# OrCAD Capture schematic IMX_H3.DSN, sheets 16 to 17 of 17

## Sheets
16 PAGE17 - discrete power supply: size C
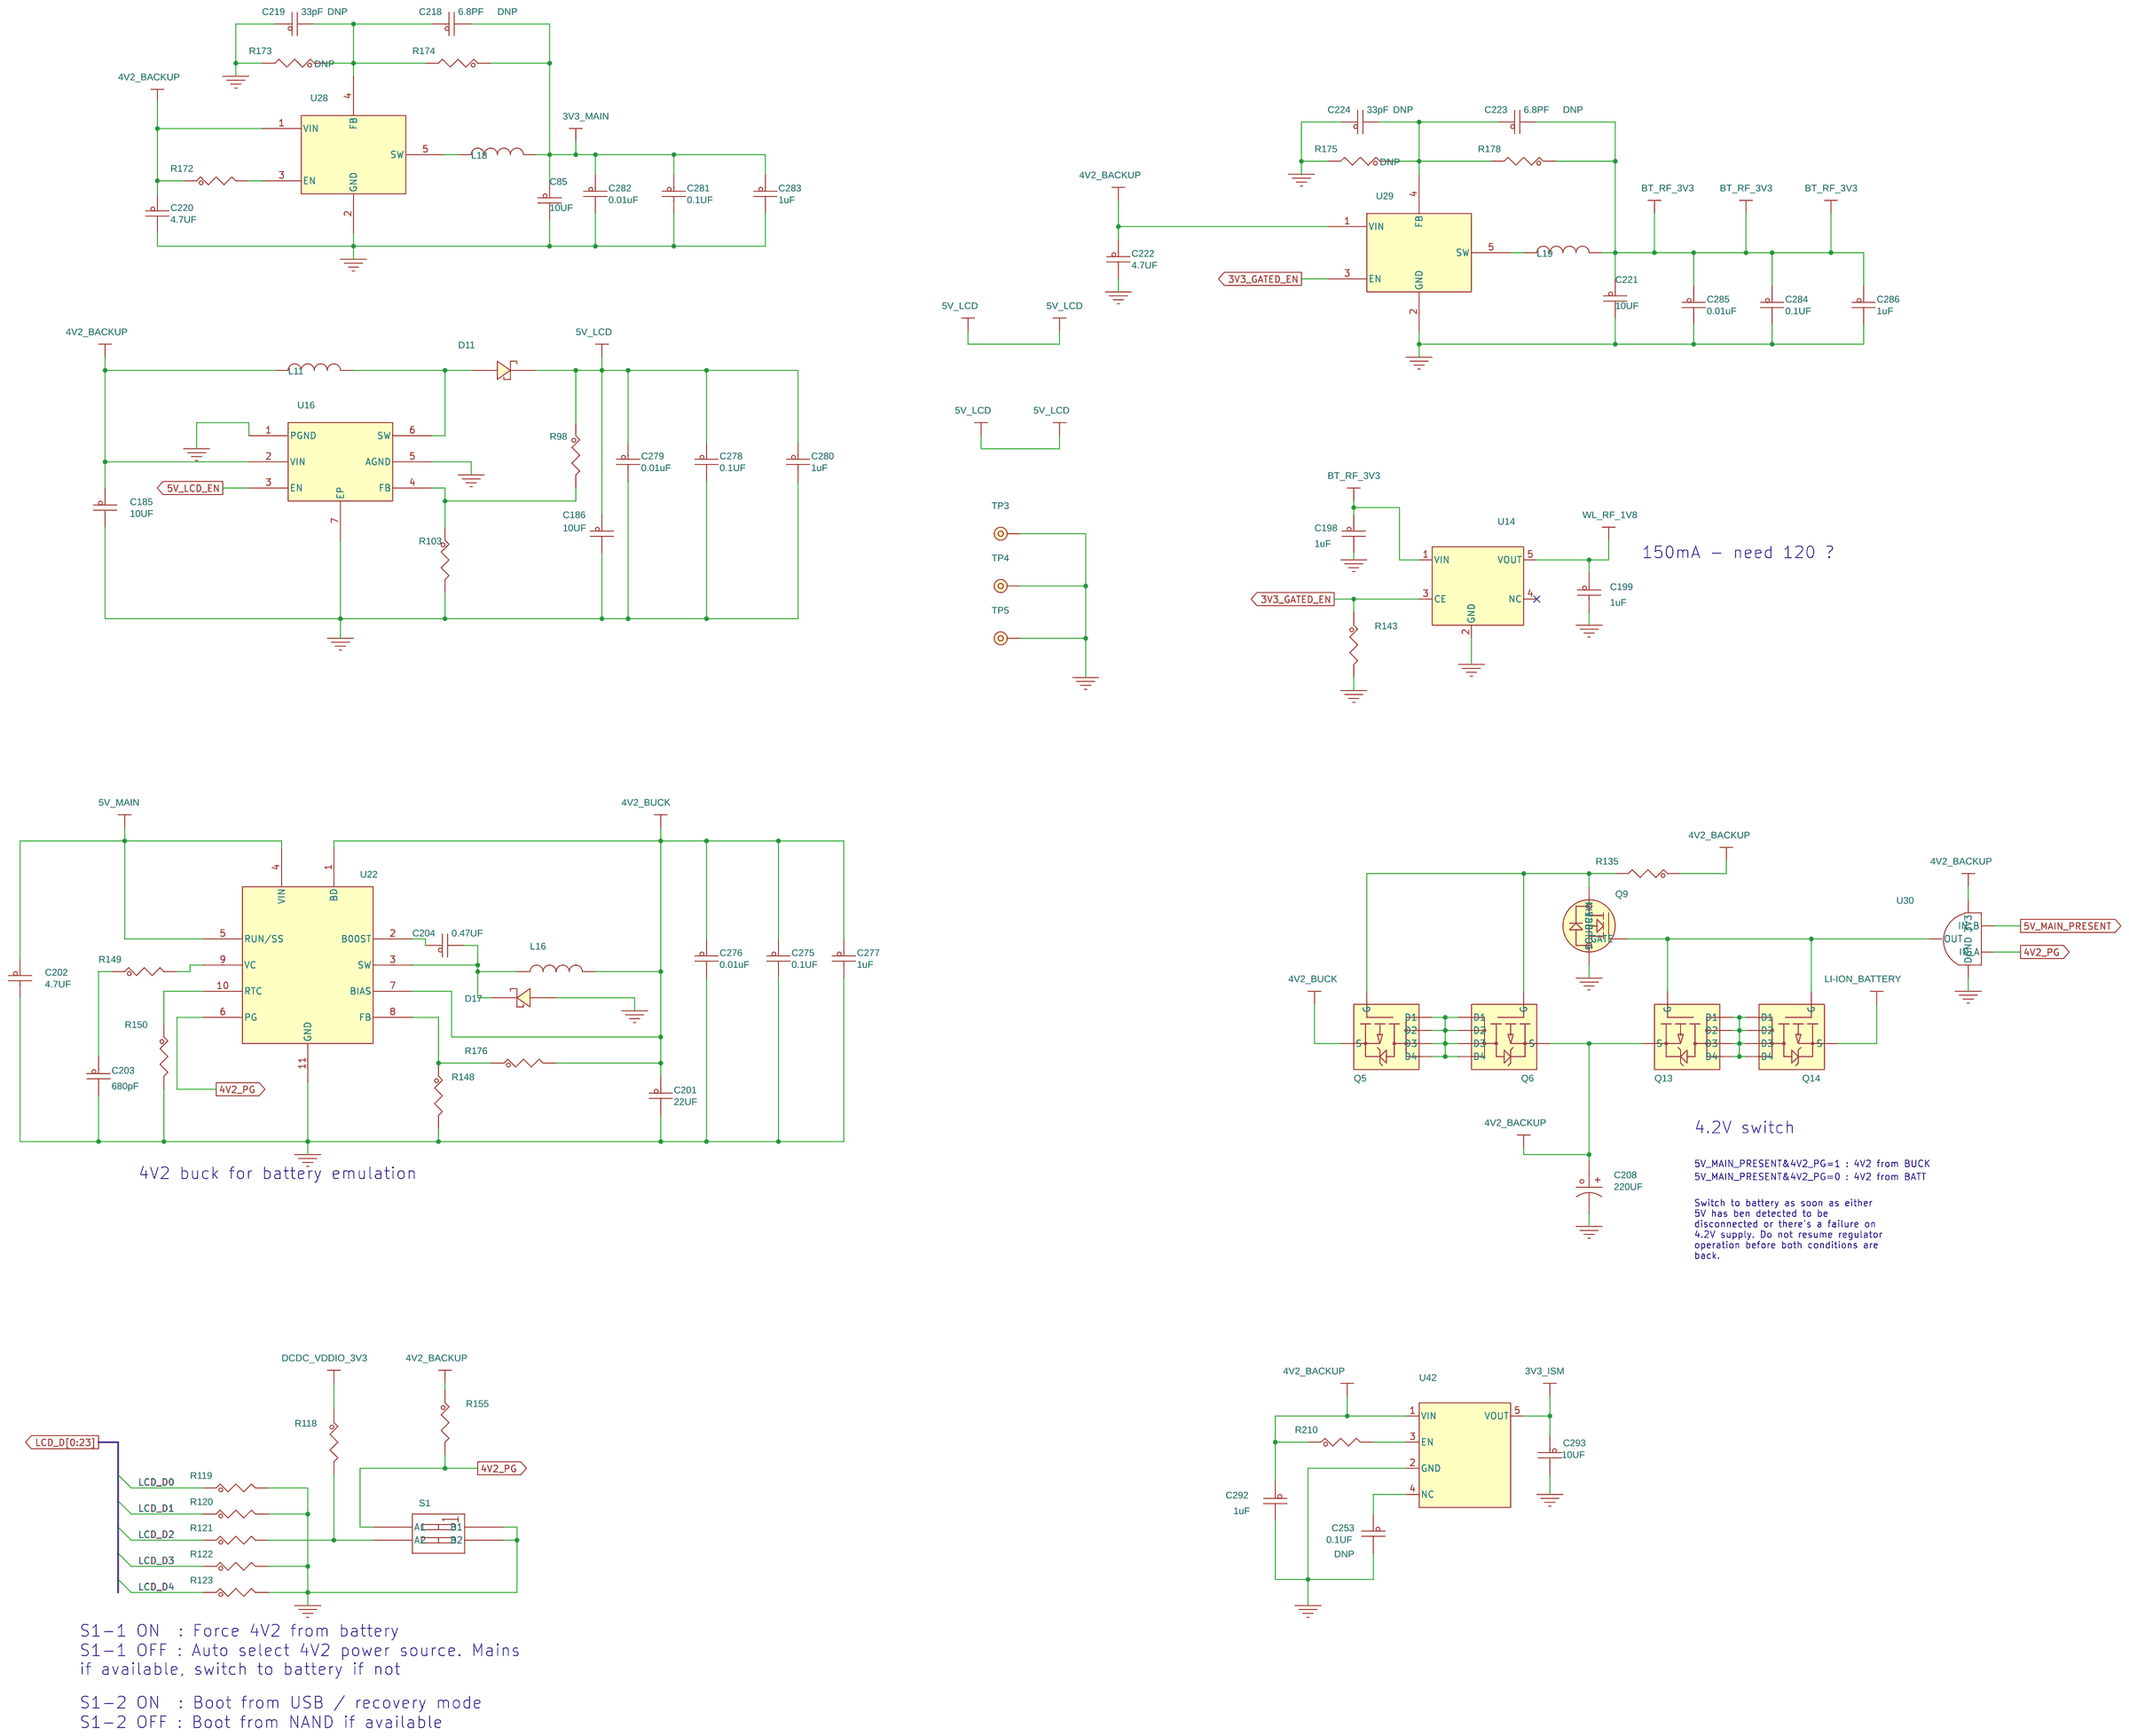
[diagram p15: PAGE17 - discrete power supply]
17 PAGE10 - CPU-DC/DC, JTAG: size C
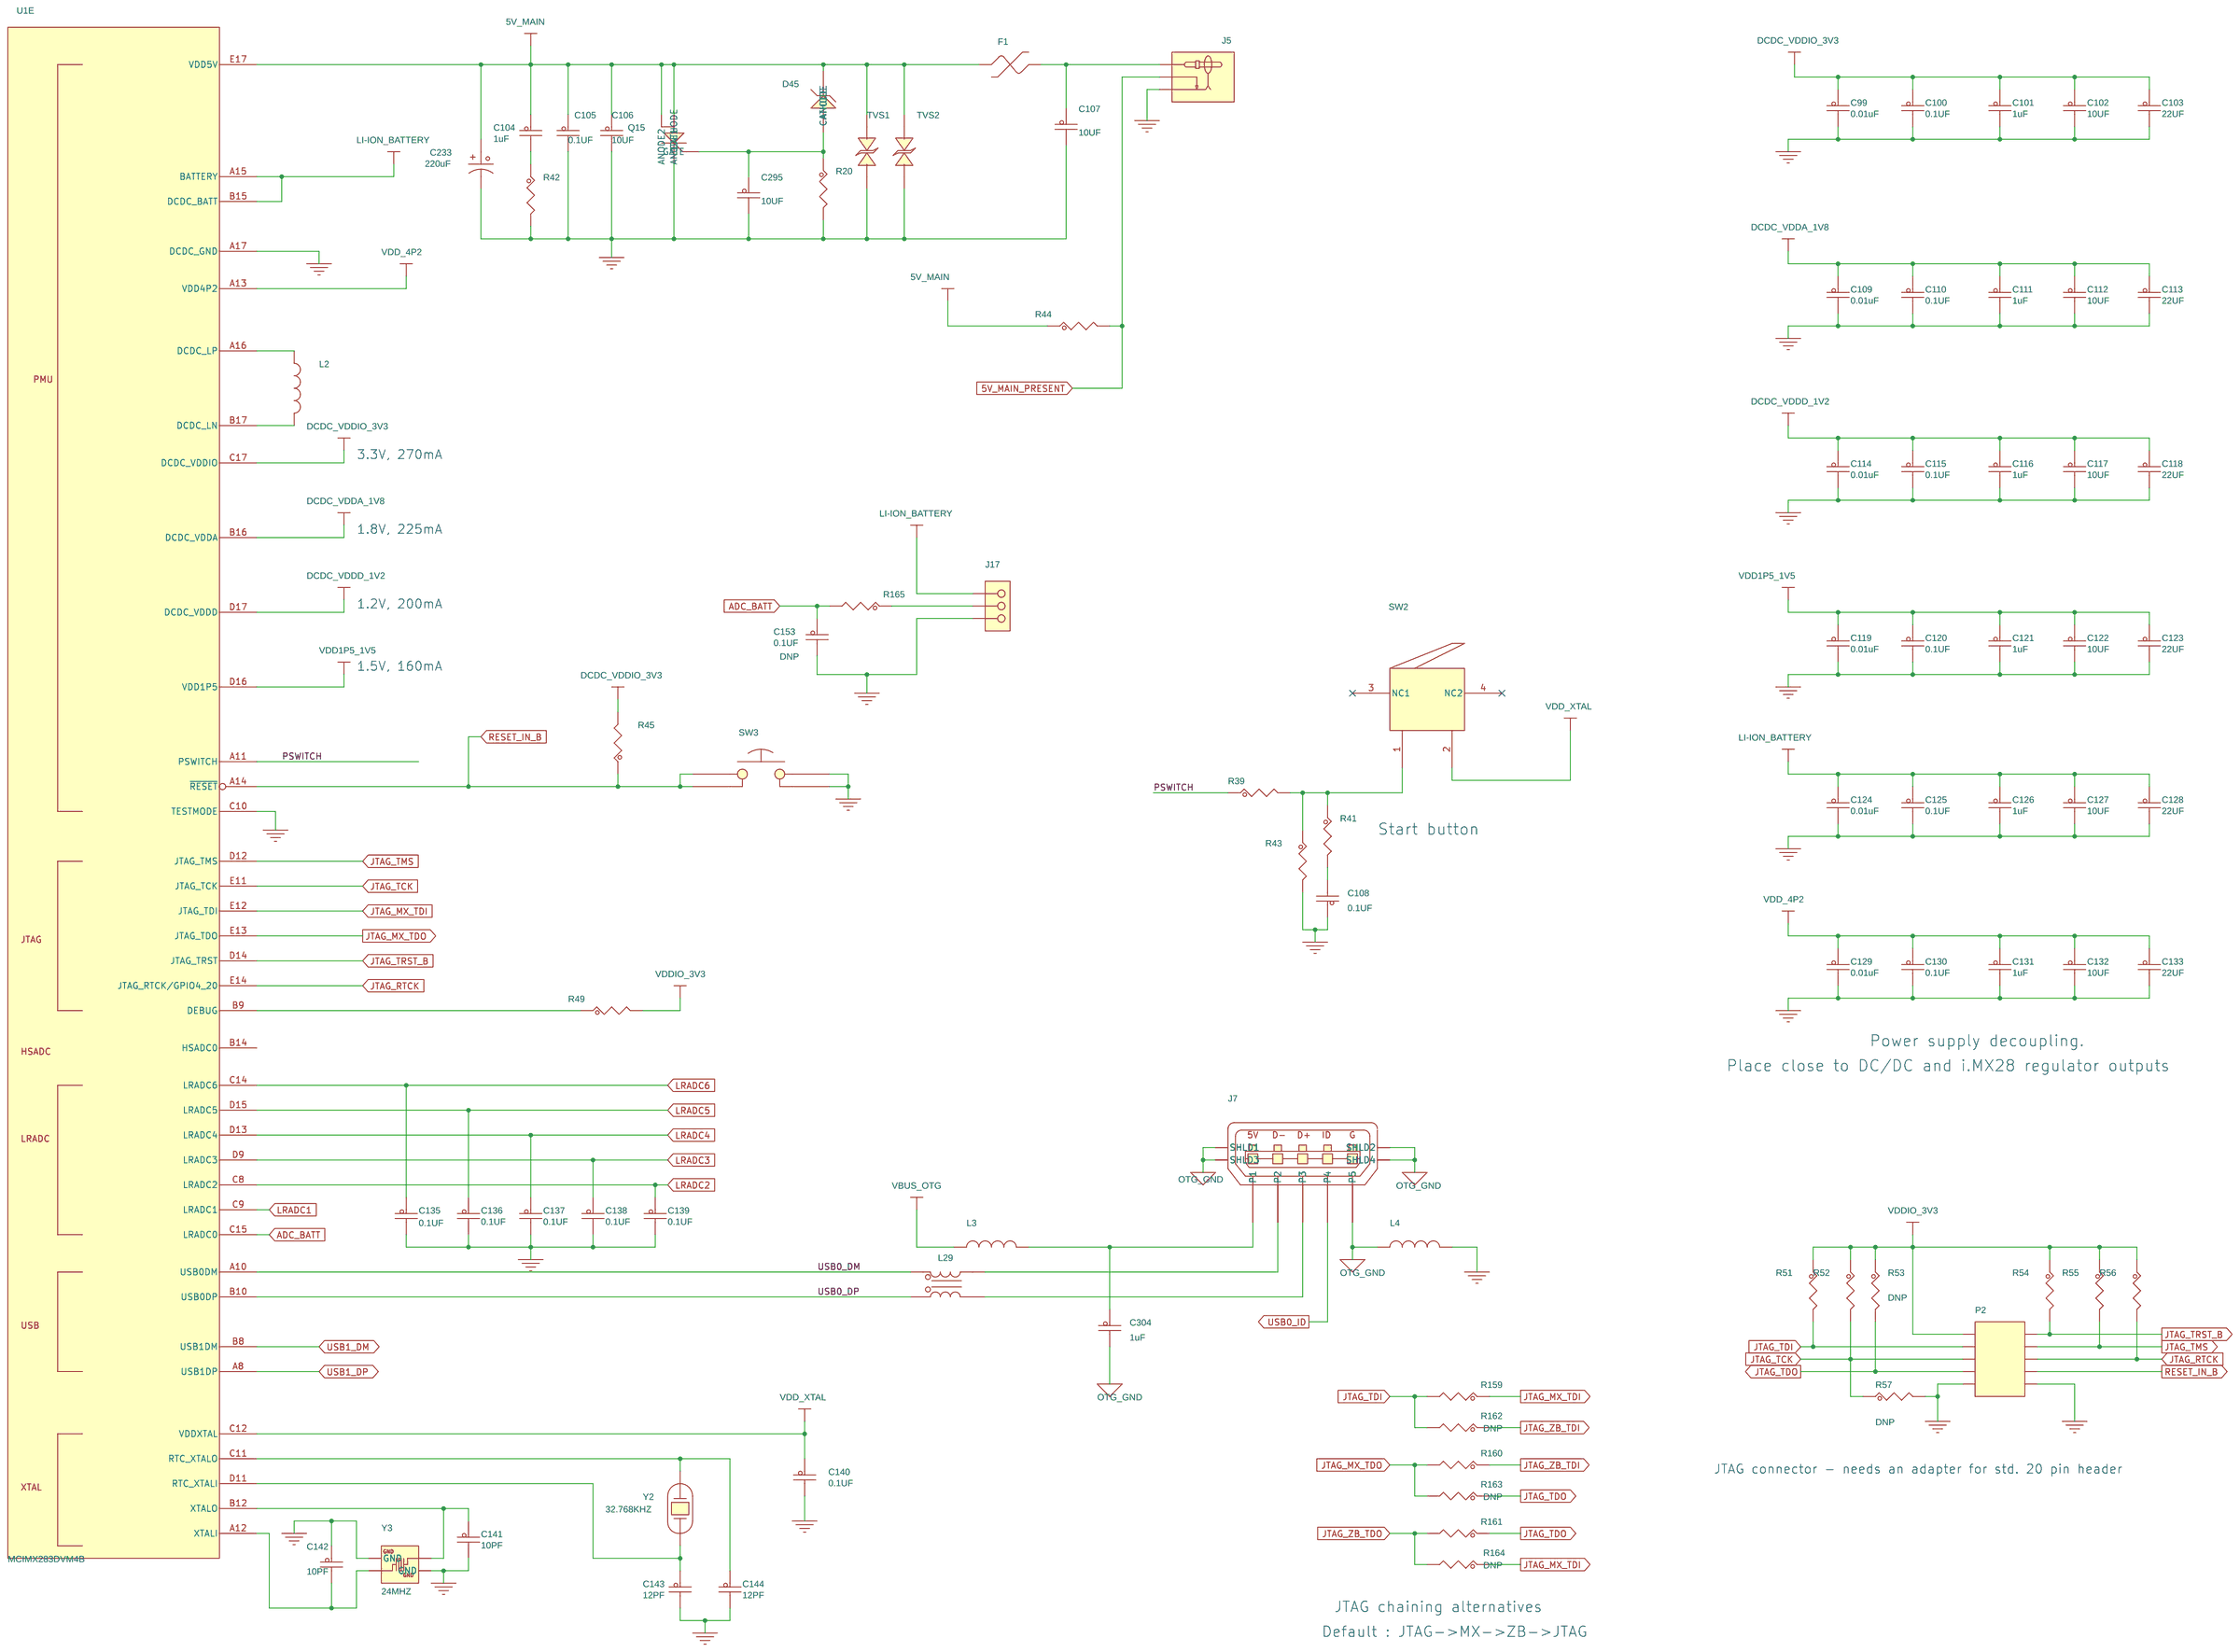
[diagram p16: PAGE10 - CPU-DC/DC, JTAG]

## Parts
sheet PAGE07 - CPU LCD & LEDs
U1  MCIMX283DVM4B  [bga289_0p8_14x14]  (sections A,B,C,D,E,F)
sheet PAGE10 - CPU-DC/DC, JTAG
C99  0.01uF  [CC0402_25]
C100  0.1UF  [CC0402_25]
C101  1uF  [CC0603_OV]
C102  10UF  [CC0805_OV]
C103  22UF  [CC0805_OV]
C104  1uF  [CC0603_OV]
C105  0.1UF  [CC0402_25]
C106  10UF  [CC0805_OV]
C107  10UF  [CC0805_OV]
C108  0.1UF  [CC0402_25]
C109  0.01uF  [CC0402_25]
C110  0.1UF  [CC0402_25]
C111  1uF  [CC0603_OV]
C112  10UF  [CC0805_OV]
C113  22UF  [CC0805_OV]
C114  0.01uF  [CC0402_25]
C115  0.1UF  [CC0402_25]
C116  1uF  [CC0603_OV]
C117  10UF  [CC0805_OV]
C118  22UF  [CC0805_OV]
C119  0.01uF  [CC0402_25]
C120  0.1UF  [CC0402_25]
C121  1uF  [CC0603_OV]
C122  10UF  [CC0805_OV]
C123  22UF  [CC0805_OV]
C124  0.01uF  [CC0402_25]
C125  0.1UF  [CC0402_25]
C126  1uF  [CC0603_OV]
C127  10UF  [CC0805_OV]
C128  22UF  [CC0805_OV]
C129  0.01uF  [CC0402_25]
C130  0.1UF  [CC0402_25]
C131  1uF  [CC0603_OV]
C132  10UF  [CC0805_OV]
C133  22UF  [CC0805_OV]
C135  0.1UF  [CC0402_25]
C136  0.1UF  [CC0402_25]
C137  0.1UF  [CC0402_25]
C138  0.1UF  [CC0402_25]
C139  0.1UF  [CC0402_25]
C140  0.1UF  [CC0402_25]
C141  10PF  [CC0402_25]
C142  10PF  [CC0402_25]
C143  12PF  [CC0402_25]
C144  12PF  [CC0402_25]
C153  0.1UF  [CC0402_25]
C233  220uF  [CC6032]
C295  10UF  [CC0805_OV]
C304  1uF  [CC0603_OV]
D45  MMSZ5231BT1G  [sod123]
F1  1.5A  [FUSE_SMDC150F]
J5  DC_POWER_JACK  [CONN_DC_POWER_3P]
J7  MICRO USB AB 5  [con5_microusb]
J17  HDR_1X3  [hdr103_78mil]
L2  15UH  [VLF5020]
L3  470OHM  [IND_0603]
L4  470OHM  [IND_0603]
L29  90 OHM@100MHZ  [IND_0805_4P]
P2  HDR 2X5  [con_2x5_fts_sm]
Q15  S602TSRP  [sot223]
R20  100  [RC0402_25]
R39  1K  [RC0402_25]
R41  1K  [RC0402_25]
R42  1  [RC0402_25]
R43  100K  [RC0402_25]
R44  470K  [RC0402_25]
R45  10.0K  [RC0402_25]
R49  10.0K  [RC0402_25]
R51  10.0K  [RC0402_25]
R52  10.0K  [RC0402_25]
R53  10.0K  [RC0402_25]
R54  10.0K  [RC0402_25]
R55  10.0K  [RC0402_25]
R56  10.0K  [RC0402_25]
R57  10.0K  [RC0402_25]
R159  0  [RC0402_25]
R160  0  [RC0402_25]
R161  0  [RC0402_25]
R162  0  [RC0402_25]
R163  0  [RC0402_25]
R164  0  [RC0402_25]
R165  0  [RC0402_25]
SW2  ATCA Handle Switch  [SW2_SPST_PB_RA]
SW3  EVQPUA02K  [sw_spst_pb_4p8x3p5_sm]
TVS1  EGA10402V05A2  [0402_mlp]
TVS2  EGA10201V00A3  [0201_CC]
Y2  32.768KHZ  [XTAL2-3P2X1P5-SM]
Y3  24MHZ  [xtlosc4_3p2x2p5mm_sm]
sheet PAGE17 - discrete power supply
C85  10UF  [CC0805_OV]
C185  10UF  [CC0805_OV]
C186  10UF  [CC0805_OV]
C198  1uF  [CC0603_OV]
C199  1uF  [CC0603_OV]
C201  22UF  [CC0805_OV]
C202  4.7UF  [CC0603_OV]
C203  680pF  [CC0402_25]
C204  0.47UF  [CC0402_25]
C208  220UF  [case_b]
C218  6.8PF  [CC0402_25]
C219  33pF  [CC0402_25]
C220  4.7UF  [CC0603_OV]
C221  10UF  [CC0805_OV]
C222  4.7UF  [CC0603_OV]
C223  6.8PF  [CC0402_25]
C224  33pF  [CC0402_25]
C253  0.1UF  [CC0402_25]
C275  0.1UF  [CC0402_25]
C276  0.01uF  [CC0402_25]
C277  1uF  [CC0603_OV]
C278  0.1UF  [CC0402_25]
C279  0.01uF  [CC0402_25]
C280  1uF  [CC0603_OV]
C281  0.1UF  [CC0402_25]
C282  0.01uF  [CC0402_25]
C283  1uF  [CC0603_OV]
C284  0.1UF  [CC0402_25]
C285  0.01uF  [CC0402_25]
C286  1uF  [CC0603_OV]
C292  1uF  [CC0603_OV]
C293  10UF  [CC0805_OV]
D11  MBR120LSFT1G  [SOD123]
D17  MBR120VLSFT1G  [SOD-123]
L11  10UH  [ind_vlf5014a]
L16  4.7UH  [ind_ihlp_2020]
L18  4.7UH  [ind_vls3012_sm]
L19  4.7UH  [ind_vls3012_sm]
Q5  NTJS4151P  [sot363]
Q6  NTJS4151P  [sot363]
Q9  NTS4001NT1G  [sc70_3]
Q13  NTJS4151P  [sot363]
Q14  NTJS4151P  [sot363]
R98  30.1K  [RC0402_25]
R103  10.0K  [RC0402_25]
R118  4.7K  [RC0402_25]
R119  47K  [RC0402_25]
R120  47K  [RC0402_25]
R121  47K  [RC0402_25]
R122  47K  [RC0402_25]
R123  47K  [RC0402_25]
R135  10.0K  [RC0402_25]
R143  10.0K  [RC0402_25]
R148  200K  [RC0402_25]
R149  16.2K  [RC0402_25]
R150  60.4K  [RC0402_25]
R155  10.0K  [RC0402_25]
R172  10.0K  [RC0402_25]
R173  0  [RC0402_25]
R174  0  [RC0402_25]
R175  0  [RC0402_25]
R176  464K  [RC0402_25]
R178  0  [RC0402_25]
R210  10.0K  [RC0402_25]
S1  SW_DIP-2/SM  [DIP-SMT2]
TP3  TEST_POINT  [testpoint_060_035mil]
TP4  TEST_POINT  [testpoint_060_035mil]
TP5  TEST_POINT  [testpoint_060_035mil]
U14  1.8V  [sot23-5_a]
U16  LM2735X  [llp6_0p95_3x3]
U22  LT1938  [dfn10]
U28  LM3671MF-3.3  [SOT23_5S]
U29  LM3671MF-3.3  [SOT23_5S]
U30  NC7SZ08P5  [SC70-5]
U42  ZXCL330E5TA  [sot23-5]

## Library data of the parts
U1 = PCIMX287DJM4A_MAPBGA_289P: IC MCU ARM926EJ-S 128KB RAM 128KB ROM 454MHZ MAPBGA289; AGILE_PN: 330-76586; CAD_APPROVED: Yes; HEIGHT: 1.37MM; MFG_NAME01: FREESCALE SEMICONDUCTOR; ROHS: Yes
C99 C109 C114 C119 C124 C129 C276 C279 C282 C285 = CAP_NP: CAP CER 0.01UF 25V 10% X7R 0402; CAD_APPROVED: Yes; FPLIST: CC0402_25,CC0402_HD,0402_CC; HEIGHT: 0.55MM; MFG_NAME01: AVX; MFG_PN01: 04023C103KAT2A; ROHS: Yes; Tolerance: 10%
C100 C105 C108 C110 C115 C120 C125 C130 C135-C140 C275 C278 C281 C284 = CAP_NP: CAP CER 0.1UF 10V 10% X5R 0402; AGILE_PN: 150-75634; CAD_APPROVED: Yes; FPLIST: CC0402_25,CC0402_HD,0402_CC; HEIGHT: 0.60MM; MFG_NAME01: KEMET; MFG_PN01: C0402C104K8PAC; ROHS: Yes; Tolerance: 10%
C101 C104 C111 C116 C121 C126 C131 C198 C199 C277 C280 C283 C286 C292 C304 = CAP_NP: CAP CER 1UF 16V 10% X7R 0603; CAD_APPROVED: Yes; FPLIST: CC0603_OV,CC0603,0603_CC; HEIGHT: 0.84mm; MFG_NAME01: TAIYO YUDEN; MFG_PN01: EMK107B7105KA-T; ROHS: Yes; Tolerance: 10%
C85 C102 C106 C107 C117 C122 C127 C132 C185 C186 C221 C293 C295 = CAP_NP: CAP CER 10UF 10V 10% X5R 0805; CAD_APPROVED: Yes; FPLIST: CC0805_OV,CC0805,0805_CC; HEIGHT: 1.45 MM; MFG_NAME01: SAMSUNG; MFG_PN01: CL21A106KPFNNNE; ROHS: Yes; Tolerance: 10%
C103 C113 C118 C123 C128 C133 C201 = CAP_NP: CAP CER 22UF 6.3V 20% X5R 0805; AGILE_PN: 150-76352; CAD_APPROVED: Yes; FPLIST: CC0805_OV,CC0805,0805_CC; HEIGHT: 1.45MM; MFG_NAME01: TDK; MFG_PN01: C2012X5R0J226M; ROHS: Yes; Tolerance: 20%
C112 = CAP_NP: CAP CER 10UF 6.3V 10% X5R 0805; CAD_APPROVED: Yes; FPLIST: CC0805_OV,CC0805,0805_CC; HEIGHT: 1.45 MM; MFG_NAME01: SAMSUNG; MFG_PN01: CL21A106KPFNNNE; ROHS: Yes; Tolerance: 10%
C141 C142 = CAP_NP: CAP CER 10PF 16V 0.25PF C0G 0402; CAD_APPROVED: Yes; FPLIST: CC0402_25,CC0402_HD,0402_CC; HEIGHT: 0.55MM; MFG_NAME01: MURATA; MFG_PN01: GRM1555C1H100JZ01D; ROHS: Yes; Tolerance: 0.25PF
C143 C144 = CAP_NP: CAP CER 12PF 50V 5% C0G 0402; CAD_APPROVED: Yes; FPLIST: CC0402_25,CC0402_HD,0402_CC; HEIGHT: 0.55MM; MFG_NAME01: MURATA; MFG_PN01: GRM1555C1H120JZ01D; ROHS: Yes; Tolerance: 5%
C153 C253 = CAP_NP: CAP CER 0.1UF 10V 10% X5R 0402; AGILE_PN: 150-75634; ASSY_OPT: DNP; CAD_APPROVED: Yes; FPLIST: CC0402_25,CC0402_HD,0402_CC; HEIGHT: 0.60MM; MFG_NAME01: KEMET; MFG_PN01: C0402C104K8PAC; ROHS: Yes; Tolerance: 10%
C233 = CAP_POL: CAP TANT ESR=0.125 OHMS 220UF 6.3V 10% 6032-28; AGILE_PN: 150-78508; CAD_APPROVED: Yes; HEIGHT: 2.8MM; MFG_NAME01: AVX; MFG_PN01: TPSC227K006R0125; ROHS: Yes; Tolerance: 10%
D45 = ZDIODE: DIODE ZNR 5.1V 0.5W SOD123; AGILE_PN: 480-76885; CAD_APPROVED: Yes; HEIGHT: 1.35MM; MFG_NAME01: ON SEMICONDUCTOR; ROHS: Yes
F1 = FUSE_RESETTABLE: FUSE PLYSW 1.5A HOLD 6V SMT ROHS; AGILE_PN: 510-75108; CAD_APPROVED: Yes; HEIGHT: 0.89MM; MFG_NAME01: TYCO ELECTRONICS; MFG_PN01: NANOSMDC150F-2; ROHS: Yes
J5 = DC_POWER_JACK_3: CON 1 PWR PLUG RA TH -- 433H -- 138L; AGILE_PN: 210-30158; CAD_APPROVED: Yes; HEIGHT: 13.5 MM; MFG_NAME01: CLIFF ELECTRONIC COMPONENTS; MFG_PN01: FC68148; ROHS: Yes
J7 = USB_MINI_AB_RECEPTACLE: CON 1X5 USB_MINI_AB_RECEPTACLE RA SMT 0.65MM SP 105H AU; AGILE_PN: 211-78722; CAD_APPROVED: Yes; HEIGHT: 2.65MM; MFG_NAME01: Molex; MFG_PN01: 47589-0001; ROHS: Yes
J17 = CONN_HDR_3X1: HDR 1X3 TH 2MM SP 217H AU 110L; AGILE_PN: 210-77092; CAD_APPROVED: Yes; HEIGHT: 5.2MM; MFG_NAME01: SAMTEC; MFG_PN01: TMM-103-02-G-S; ROHS: Yes
L2 = INDUCTOR: IND PWR 15UH@100KHZ 0.9A 20% SMT; AGILE_PN: 180-76976; CAD_APPROVED: Yes; HEIGHT: 2.0MM; MFG_NAME01: TDK; MFG_PN01: VLCF5020T-150MR90-1; PART_TYPE: COIL; ROHS: Yes
L3 L4 = INDUCTOR: IND FER BEAD 470OHM@100MHZ 500MA 25% 0603; AGILE_PN: 180-76158; CAD_APPROVED: Yes; FPLIST: IND_0603,0603_CC; HEIGHT: 0.95MM; MFG_NAME01: MURATA; MFG_PN01: BLM18EG471SN1D; ROHS: Yes; Tolerance: 25%
L29 = 42H171000: IND CHOKE USB2.0 90OHM@100MHz 500mA SMT 0805; AGILE_PN: 180-77702; CAD_APPROVED: Yes; HEIGHT: 1.65MM; MFG_NAME01: COILCRAFT; MFG_PN01: 0805USB-901MLC; PART_TYPE: CHOKE; ROHS: Yes
P2 = CONN_PCB_2X5: HDR 2X5 SMT 1.27MM CTR 125H AU; AGILE_PN: 211-30081; CAD_APPROVED: Yes; HEIGHT: 4.32MM; MFG_NAME01: SAMTEC; MFG_PN01: FTS-105-01-L-DV-P; ROHS: Yes
Q15 = TRIAC_2A: THYRISTOR 1.5A 600V SOT223; AGILE_PN: TMP-WF-15634; CAD_APPROVED: Yes; HEIGHT: 1.9MM; MFG_NAME01: LITTELFUSE; PRE_APN: 480-78250; ROHS: Yes
R20 = RES: RES MF 100 OHM 1/16W 1% 0402; CAD_APPROVED: Yes; FPLIST: RC0402_25,RC0402_HD,0402_CC; MFG_NAME01: Yageo; MFG_PN01: RC0402FR-07100RL; ROHS: Yes; Tolerance: 1%
R39 R41 = RES: RES MF 1.0K 1/16W 5% 0402; AGILE_PN: 470-75555; CAD_APPROVED: Yes; FPLIST: RC0402_25,RC0402_HD,RC0402_X2,0402_CC; MFG_NAME01: VISHAY INTERTECHNOLOGY; MFG_PN01: CRCW04021K00JNED; ROHS: Yes; Tolerance: 5%
R42 = RES: RES MF 1.0 OHM 1/16W 5% 0402; CAD_APPROVED: Yes; FPLIST: RC0402_25,RC0402_HD,0402_CC; MFG_NAME01: VISHAY; MFG_PN01: CRCW04021R00JNED; ROHS: Yes; Tolerance: 5%
R43 = RES: RES MF 100K 1/16W 5% 0402; AGILE_PN: 470-75597; CAD_APPROVED: Yes; FPLIST: RC0402_25,RC0402_HD,0402_CC; MFG_NAME01: KOA SPEER; MFG_PN01: RK73B1ETTP104J; ROHS: Yes; Tolerance: 5%
R44 = RES: RES MF 470K  1/16W 1% 0402; AGILE_PN: 470-31136; CAD_APPROVED: Yes; FPLIST: RC0402_25,RC0402_HD,0402_CC; MFG_NAME01: KOA SPEER; MFG_PN01: RK73H1ETTP4703F; ROHS: Yes; Tolerance: 1%
R45 R49 R51 R52 R54-R56 R103 R135 R143 R155 R172 R210 = RES: RES MF 10.0K 1/16W 1% 0402; AGILE_PN: 470-75416; CAD_APPROVED: Yes; FPLIST: RC0402_25,RC0402_HD,0402_CC; MFG_NAME01: KOA SPEER; MFG_PN01: RK73H1ETTP1002F; ROHS: Yes; Tolerance: 1%
R53 R57 = RES: RES MF 10.0K 1/16W 1% 0402; AGILE_PN: 470-75416; ASSY_OPT: DNP; CAD_APPROVED: Yes; FPLIST: RC0402_25,RC0402_HD,0402_CC; MFG_NAME01: KOA SPEER; MFG_PN01: RK73H1ETTP1002F; ROHS: Yes; Tolerance: 1%
R159-R161 R165 R174 R178 = RES: RES MF ZERO OHM 1/16W 5% 0402; AGILE_PN: 470-75394; CAD_APPROVED: Yes; FPLIST: RC0402_25,RC0402_HD,RC0402_X2,0402_CC; MFG_NAME01: ROHM; MFG_PN01: MCR01MZPJ000; ROHS: Yes; Tolerance: 5%
R162-R164 R173 R175 = RES: RES MF ZERO OHM 1/16W 5% 0402; AGILE_PN: 470-75394; ASSY_OPT: DNP; CAD_APPROVED: Yes; FPLIST: RC0402_25,RC0402_HD,RC0402_X2,0402_CC; MFG_NAME01: ROHM; MFG_PN01: MCR01MZPJ000; ROHS: Yes; Tolerance: 5%
SW2 = SW2_SPST_PB: SW SPDT 100MILLIAMPS@12VDC; AGILE_PN: 510-75076; CAD_APPROVED: Yes; HEIGHT: 2MM; MFG_NAME01: ITT CANNON; MFG_PN01: SDS001; ROHS: Yes
SW3 = EDGE_MOUNT_PB_SW_2: SW SPST NO PB 2.2N SIDE 12V 50MA SMT; AGILE_PN: 510-76838; CAD_APPROVED: Yes; HEIGHT: 1.95MM; MFG_NAME01: PANASONIC; ROHS: Yes
TVS1 = DIODE_TVS_BIDIR: DIODE TVS ESD -- -- 0402; CAD_APPROVED: Yes; HEIGHT: 0.48MM; MFG_NAME01: INPAQ TECHNOLOGY (SUZHOU) CO., LTD; MFG_PN01: EGA10402V05AH; ROHS: Yes
TVS2 = DIODE_TVS_BIDIR: DIODE TVS ESD -- -- 0201; AGILE_PN: 480-77357; CAD_APPROVED: Yes; HEIGHT: 0.48MM; MFG_NAME01: INPAQ TECHNOLOGY (SUZHOU) CO., LTD; ROHS: Yes
Y2 = XTAL: XTAL 32.768KHZ 12.5PF 20PPM 3.2X1.5MM SMT; AGILE_PN: 230-77653; CAD_APPROVED: Yes; HEIGHT: 0.9MM; MFG_NAME01: Abracon Corporation; MFG_PN01: ABS07-32.768KHZ-T; ROHS: Yes
Y3 = CRYSTAL_JXS63: XTAL 24MHZ -- 30PPM 3.2X2.5MM SMD; AGILE_PN: 230-77452; CAD_APPROVED: Yes; HEIGHT: 0.9MM; MFG_NAME01: TXC CORP; MFG_PN01: 7V-24.000MAAE-T; ROHS: Yes
C202 C220 C222 = CAP_NP: CAP CER 4.7UF 6.3V 10% X5R 0603; CAD_APPROVED: Yes; FPLIST: CC0603_OV,CC0603,0603_CC; HEIGHT: 0.95MM; MFG_NAME01: Murata; MFG_PN01: GRM188R60J475KE19D; ROHS: Yes; Tolerance: 10%
C203 = CAP_NP: CAP CER 680PF 50V 10% X5R 0402; CAD_APPROVED: Yes; FPLIST: CC0402_25,CC0402_HD,0402_CC; HEIGHT: 0.55MM; MFG_NAME01: Murata; MFG_PN01: GRM155R71H681KA01D; ROHS: Yes; Tolerance: 10%
C204 = CAP_NP: CAP CER 0.47UF 6.3V 10% X5R 0402; AGILE_PN: 150-77952; CAD_APPROVED: Yes; FPLIST: CC0402_25,CC0402_HD,0402_CC; HEIGHT: 0.55MM; MFG_NAME01: Murata; MFG_PN01: GRM155R60J474KE19D; ROHS: Yes; Tolerance: 10%
C208 = CAP_POL: CAP TANT ESR=0.400 OHM 220UF 6.3V 20% -- 3327-18; AGILE_PN: 150-78530; CAD_APPROVED: Yes; HEIGHT: 2.0MM; MFG_NAME01: Nichicon; MFG_PN01: F950J227MBAAQ2; ROHS: Yes; Tolerance: 20%
C218 C223 = CAP_NP: CAP CER 6.8PF 50V 0.5PF C0G 0402; ASSY_OPT: DNP; CAD_APPROVED: Yes; FPLIST: CC0402_25,CC0402_HD,0402_CC; HEIGHT: 0.55MM; MFG_NAME01: MURATA; MFG_PN01: GRM1555C1H6R8DZ01D; ROHS: Yes; Tolerance: 0.5PF %
C219 C224 = CAP_NP: CAP CER 33PF 50V 5% C0G 0402; ASSY_OPT: DNP; CAD_APPROVED: Yes; FPLIST: CC0402_25,CC0402_HD,0402_CC; HEIGHT: 0.635 MM; MFG_NAME01: TDK; MFG_PN01: C1005C0G1H330J; ROHS: Yes; Tolerance: 5%
D11 = DIODE_SCHTKY: DIODE SCH PWR RECT 1A 20V SMT; AGILE_PN: 480-75210; CAD_APPROVED: YES; HEIGHT: 1.0MM; MFG_NAME01: ON SEMICONDUCTOR; ROHS: Yes
D17 = DIODE_SCHTKY: DIODE SCH RECT 1A 20V SMT; AGILE_PN: 480-75997; CAD_APPROVED: Yes; HEIGHT: 1MM; MFG_NAME01: ON SEMICONDUCTOR; ROHS: Yes
L11 = INDUCTOR: IND PWR 10UH@100KHZ 1.1A 20% SMT; AGILE_PN: 180-76524; CAD_APPROVED: Yes; HEIGHT: 1.40MM; MFG_NAME01: TDK; MFG_PN01: VLF5014AT-100MR92; ROHS: Yes; Tolerance: 20%
L16 = INDUCTOR: IND PWR 4.7UH@100KHZ 2.8A 20% SMT; AGILE_PN: 180-77611; CAD_APPROVED: Yes; HEIGHT: 2MM; MFG_NAME01: VISHAY INTERTECHNOLOGY; MFG_PN01: IHLP2020BZER4R7M01; PART_TYPE: INDUCTOR\POWER; ROHS: Yes; Tolerance: 20%
L18 L19 = INDUCTOR: IND PWR 4.7UH@1MHZ 1A 20% SMD; AGILE_PN: 180-77706; CAD_APPROVED: Yes; HEIGHT: 1.2MM; MFG_NAME01: TDK; MFG_PN01: VLS3012T-4R7M1R0; PART_TYPE: INDUCTOR\POWER; ROHS: Yes; Tolerance: 20%
Q5 Q6 Q13 Q14 = MOSFET_P_6P: TRAN PMOS PWR 20V 4.2A SOT363; AGILE_PN: 480-75984; CAD_APPROVED: Yes; HEIGHT: 1.1MM; MFG_NAME01: ON SEMICONDUCTOR; MFG_PN01: NTJS4151PT1G; ROHS: Yes
Q9 = MOSFET_N: TRAN NMOS SW 30V 270MA SC-70; AGILE_PN: 480-76278; CAD_APPROVED: Yes; HEIGHT: 1.0MM; MFG_NAME01: ON SEMICONDUCTOR; ROHS: Yes
R98 = RES: RES MF 30.1K  1/16W 1% 0402; AGILE_PN: 470-31000; CAD_APPROVED: Yes; FPLIST: RC0402_25,RC0402_HD,0402_CC; MFG_NAME01: KOA SPEER; MFG_PN01: RK73H1ETTP3012F; ROHS: Yes; Tolerance: 1%
R118 = RES: RES MF 4.70K 1/16W 1% 0402; CAD_APPROVED: Yes; FPLIST: RC0402_25,RC0402_HD,0402_CC; MFG_NAME01: VISHAY; MFG_PN01: CRCW04024K70FKED; ROHS: Yes; Tolerance: 1%
R119-R123 = RES: RES MF 47K 1/16W 5% 0402; CAD_APPROVED: Yes; FPLIST: RC0402_25,RC0402_HD,0402_CC; MFG_NAME01: VISHAY; MFG_PN01: CRCW040247K0JNED; ROHS: Yes; Tolerance: 5%
R148 = RES: RES MF 200K  1/16W 1% 0402; AGILE_PN: 470-31093; CAD_APPROVED: Yes; FPLIST: RC0402_25,RC0402_HD,0402_CC; MFG_NAME01: KOA SPEER; MFG_PN01: RK73H1ETTP2003F; ROHS: Yes; Tolerance: 1%
R149 = RES: RES MF 16.2K 1/16W 1% 0402; AGILE_PN: 470-76206; CAD_APPROVED: Yes; FPLIST: RC0402_25,RC0402_HD,0402_CC; MFG_NAME01: KOA SPEER; MFG_PN01: RK73H1ETTP1622F; ROHS: Yes; Tolerance: 1%
R150 = RES: RES MF 60.4K  1/16W 1% 0402; AGILE_PN: 470-31036; CAD_APPROVED: Yes; FPLIST: RC0402_25,RC0402_HD,0402_CC; MFG_NAME01: KOA SPEER; MFG_PN01: RK73H1ETTP6042F; ROHS: Yes; Tolerance: 1%
R176 = RES: RES MF 464K  1/16W 1% 0402; AGILE_PN: 470-31135; CAD_APPROVED: Yes; FPLIST: RC0402_25,RC0402_HD,0402_CC; MFG_NAME01: KOA SPEER; MFG_PN01: RK73H1ETTP4643F; ROHS: Yes; Tolerance: 1%
S1 = SW_DIP-2: SW SPST DIP SMT 30V 10MA; AGILE_PN: 510-30009; CAD_APPROVED: Yes; HEIGHT: 4.83 MM; MFG_NAME01: GRAYHILL; MFG_PN01: 90HBW02PRT; ROHS: Yes
TP3-TP5 = T_POINT_TH: TEST POINT TH PAD 60 DRILL 35 DIAM, NO PART TO ORDER; AGILE_PN: 210-78939; CAD_APPROVED: Yes; HEIGHT: 0.1MM; MFG_NAME01: NA; MFG_PN01: NO PART TO ORDER; ROHS: Yes
U14 = MC78PC18NTR_1: IC VREG LIN LDO 1.8V, 150 MA SOT23-5; AGILE_PN: 315-75444; CAD_APPROVED: Yes; HEIGHT: 1.4MM; MFG_NAME01: ON SEMICONDUCTOR; MFG_PN01: MC78PC18NTRG; ROHS: Yes
U16 = LM2735XSD: IC VREG BOOST/SEPIC DC-DC 1.6MHZ 3.0-24V 2.1A 2.7-5.5V LLP6; AGILE_PN: 315-78806; CAD_APPROVED: Yes; HEIGHT: 0.8MM; MFG_NAME01: National Semiconductor; MFG_PN01: LM2735XSD/NOPB; ROHS: Yes
U22 = LT1938_DFN10: IC VREG SWT 3.3V 2.2A 25V DFN10; AGILE_PN: TMP-WF-13732; CAD_APPROVED: Yes; HEIGHT: 0.75 MM; MFG_NAME01: Linear Technology; MFG_PN01: LT1938EDD#PBF; PRE_APN: 312-80005; ROHS: Yes
U28 U29 = LM3671: IC LIN DCDC 3.3V 600MA 2.7V-5.5V SOT23-5; AGILE_PN: 315-78907; CAD_APPROVED: Yes; HEIGHT: 1.22MM; MFG_NAME01: National semiconductor; MFG_PN01: LM3671MF-3.3/NOPB; ROHS: Yes
U30 = ONE_AND: IC GATE AND SGL 2-INP UHS 1.65-5.5V SC70-5; AGILE_PN: 312-30302; CAD_APPROVED: Yes; HEIGHT: 1.1MM; MFG_NAME01: FAIRCHILD; MFG_PN01: NC7SZ08P5_NL; ROHS: Yes
U42 = ZXCL330E5TA: IC VREG LDO 3.3V 150MA 3.8-5.5V SOT23-5; AGILE_PN: 315-77605; CAD_APPROVED: Yes; HEIGHT: 1.45MM; MFG_NAME01: Zetex Inc; ROHS: Yes

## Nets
3V3_GATED: C198.1 C221.1 C223.2 C284.1 C285.1 C286.1 L19.2 R178.1 U14.1(VIN) ; also on sheet 6 11 12 13 15
3V3_GATED_EN: R143.1 U14.3(CE) U29.3(EN) ; also on sheet 15
3V3_ISM: C293.1 U42.5(VOUT) ; also on sheet 10
3V3_MAIN: C85.1 C218.2 C281.1 C282.1 C283.1 L18.2 R174.1 ; also on sheet 7 14
4V2_BACKUP: C185.1 C208.1 C220.1 C222.1 C292.1 L11.1 Q6.4(S) Q13.4(S) R135.1 R155.1 R172.1 R210.1 U16.2(VIN) U28.1(VIN) U29.1(VIN) U30.5(3V3) U42.1(VIN) ; also on sheet 14
4V2_BUCK: C201.1 C275.1 C276.1 C277.1 L16.2 Q5.4(S) R176.2 U22.1(BD) U22.7(BIAS)
4V2_PG: R155.2 S1.1(A1) U22.6(PG) U30.2(IN_A)
5V: C186.1 C278.1 C279.1 C280.1 D11.C R98.1 ; also on sheet 7
5V_LCD_EN: U16.3(EN) ; also on sheet 15
5V_MAIN: C104.1 C105.1 C106.1 C202.1 C233.1 D45.C(CATHODE) F1.1 Q15.2(ANODE1) Q15.4(ANODE2) R44.1 TVS1.2 TVS2.2 U1.E17(VDD5V) U22.4(VIN) U22.5(RUN/SS)
5V_MAIN_PRESENT: J5.2 R44.2 U30.1(IN_B) ; also on sheet 8
GND: C85.2 C99.2 C100.2 C101.2 C102.2 C103.2 C105.2 C106.2 C107.2 C108.1 C109.2 C110.2 C111.2 C112.2 C113.2 C114.2 C115.2 C116.2 C117.2 C118.2 C119.2 C120.2 C121.2 C122.2 C123.2 C124.2 C125.2 C126.2 C127.2 C128.2 C129.2 C130.2 C131.2 C132.2 C133.2 C135.2 C136.2 C137.2 C138.2 C139.2 C140.2 C141.2 C142.1 C143.2 C144.2 C153.2 C185.2 C186.2 C198.2 C199.2 C201.2 C202.2 C203.2 C208.2 C219.1 C220.2 C221.2 C222.2 C224.1 C233.2 C253.2 C275.2 C276.2 C277.2 C278.2 C279.2 C280.2 C281.2 C282.2 C283.2 C284.2 C285.2 C286.2 C292.2 C293.2 C295.2 D17.A J5.3 J17.3 L4.2 P2.9 P2.10 Q9.2(SOURCE) Q15.1(CATHODE) R20.2 R42.2 R43.2 R57.2 R103.2 R119.2 R120.2 R122.2 R123.2 R143.2 R148.2 R150.2 R173.2 R175.2 S1.3(B2) S1.4(B1) SW3.2 SW3.4 TP3.1(TP) TP4.1(TP) TP5.1(TP) TVS1.1 TVS2.1 U1.A17(DCDC_GND) U1.C10(TESTMODE) U14.2(GND) U16.1(PGND) U16.5(AGND) U16.7(EP) U22.11(GND) U28.2(GND) U29.2(GND) U30.3(DGND) U42.2(GND) Y3.2(GND) Y3.4(GND) ; also on sheet 5 6 7 8 9 10 11 12 13 14 15
VBUS_OTG: L3.1 ; also on sheet 7 14
VDD1P5_1V5: C119.1 C120.1 C121.1 C122.1 C123.1 U1.D16(VDD1P5)
VDD_4P2: C129.1 C130.1 C131.1 C132.1 C133.1 U1.A13(VDD4P2)
VDD_XTAL: C140.1 SW2.2 U1.C12(VDDXTAL)
ADC_BATT: C153.1 R165.2 U1.C15(LRADC0)
DCDC_VDDA_1V8: C109.1 C110.1 C111.1 C112.1 C113.1 U1.B16(DCDC_VDDA) ; also on sheet 5 7 9
DCDC_VDDD_1V2: C114.1 C115.1 C116.1 C117.1 C118.1 U1.D17(DCDC_VDDD) ; also on sheet 9
DCDC_VDDIO_3V3: C99.1 C100.1 C101.1 C102.1 C103.1 P2.1 R45.2 R49.2 R51.1 R52.1 R53.1 R54.1 R55.1 R56.1 R118.1 U1.C17(DCDC_VDDIO) ; also on sheet 6 7 8 9 10 12 13 14 15
JTAG_MX_TDI: R159.1 R164.1 U1.E12(JTAG_TDI)
JTAG_MX_TDO: R160.2 R163.2 U1.E13(JTAG_TDO)
JTAG_RTCK: P2.6 R56.2 U1.E14(JTAG_RTCK/GPIO4_20) ; also on sheet 11
JTAG_TCK: P2.5 R52.2 R57.1 U1.E11(JTAG_TCK) ; also on sheet 11
JTAG_TDI: P2.3 R51.2 R159.2 R162.2
JTAG_TDO: P2.7 R53.2 R161.1 R163.1
JTAG_TMS: P2.4 R55.2 U1.D12(JTAG_TMS) ; also on sheet 11
JTAG_TRST_B: P2.2 R54.2 U1.D14(JTAG_TRST) ; also on sheet 11
JTAG_ZB_TDI: R160.1 R162.1 ; also on sheet 11
JTAG_ZB_TDO: R161.2 R164.2 ; also on sheet 11
LCD_D0: R119.1 ; also on sheet 7
LCD_D1: R120.1 ; also on sheet 7
LCD_D2: R121.1 ; also on sheet 7
LCD_D3: R122.1 ; also on sheet 7
LCD_D4: R123.1 ; also on sheet 7
LI-ION_BATTERY: C124.1 C125.1 C126.1 C127.1 C128.1 J17.1 Q14.4(S) U1.A15(BATTERY) U1.B15(DCDC_BATT) ; also on sheet 7
LRADC1: U1.C9(LRADC1)
LRADC2: C139.1 U1.C8(LRADC2) ; also on sheet 7
LRADC3: C138.1 U1.D9(LRADC3) ; also on sheet 7
LRADC4: C137.1 U1.D13(LRADC4) ; also on sheet 7
LRADC5: C136.1 U1.D15(LRADC5) ; also on sheet 7
LRADC6: C135.1 U1.C14(LRADC6) ; also on sheet 7
OTG_GND: C304.2 J7.5(P5) J7.S1(SHLD1) J7.S2(SHLD2) J7.S3(SHLD3) J7.S4(SHLD4) L4.1
PSWITCH: R39.1 U1.A11(PSWITCH)
RESET_IN_B: P2.8 R45.1 SW3.1 SW3.3 U1.A14(~{RESET})
USB0_DM: L29.1 U1.A10(USB0DM)
USB0_DP: L29.4 U1.B10(USB0DP)
USB0_ID: J7.4(P4) ; also on sheet 6
USB1_DM: U1.B8(USB1DM) ; also on sheet 14
USB1_DP: U1.A8(USB1DP) ; also on sheet 14
WL_RF_1V8: C199.1 U14.5(VOUT) ; also on sheet 13
N20787959: L2.1 U1.A16(DCDC_LP)
N20788242: L2.2 U1.B17(DCDC_LN)
N21052242: R49.1 U1.B9(DEBUG)
N21053866: C142.2 U1.A12(XTALI) Y3.1
N21053884: C141.1 U1.B12(XTALO) Y3.3
N21906184: C107.1 F1.2 J5.1
N22878041: C108.2 R41.2
N22880531: R39.2 R41.1 R43.1 SW2.1
N24090083: C143.1 U1.D11(RTC_XTALI) Y2.1
N24109192: C144.1 U1.C11(RTC_XTALO) Y2.2
N25260991: C304.1 J7.1(P1) L3.2
N27366059: C104.2 R42.1
N28006980: Q9.1(GATE) Q13.3(G) Q14.3(G) U30.4(OUT)
N28006984: Q5.1(D1) Q5.2(D2) Q5.5(D3) Q5.6(D4) Q6.1(D1) Q6.2(D2) Q6.5(D3) Q6.6(D4)
N28007052: Q13.1(D1) Q13.2(D2) Q13.5(D3) Q13.6(D4) Q14.1(D1) Q14.2(D2) Q14.5(D3) Q14.6(D4)
N28007071: Q5.3(G) Q6.3(G) Q9.3(DRAIN) R135.2
N28007120: C204.1 U22.2(B00ST)
N28007130: C204.2 D17.C L16.1 U22.3(SW)
N28007178: R149.2 U22.9(VC)
N28007224: C203.1 R149.1
N28007244: R150.1 U22.10(RTC)
N28007274: R148.1 R176.1 U22.8(FB)
N28567011: L18.1 U28.5(SW)
N28574144: R172.2 U28.3(EN)
N28583550: C218.1 C219.2 R173.1 R174.2 U28.4(FB)
N28633938: C223.1 C224.2 R175.1 R178.2 U29.4(FB)
N28634078: L19.1 U29.5(SW)
N28870429: D11.A L11.2 U16.6(SW)
N28870443: R98.2 R103.1 U16.4(FB)
N28879486: R118.2 R121.2 S1.2(A2)
N29031770: J7.3(P3) L29.3
N29031779: J7.2(P2) L29.2
N29031855: J17.2 R165.1
N29085144: C253.1 U42.4(NC)
N29085154: R210.2 U42.3(EN)
N29128269: C295.1 D45.A(ANODE) Q15.3(GATE) R20.1

Not connected (* = marked no-connect by the designer): SW2 3(NC1)* 4(NC2)*; U1 B14(HSADC0); U14 4(NC)*

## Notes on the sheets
sheet 16
- 150mA - need 120 ?
- 4.2V switch
- 4V2 buck for battery emulation
- 5V_MAIN_PRESENT&4V2_PG=0 : 4V2 from BATT
- 5V_MAIN_PRESENT&4V2_PG=1 : 4V2 from BUCK
- Switch to battery as soon as either
  5V has ben detected to be
  disconnected or there's a failure on
  4.2V supply. Do not resume regulator
  operation before both conditions are
  back.
- S1-1 ON  : Force 4V2 from battery
- S1-1 OFF : Auto select 4V2 power source. Mains
  if available, switch to battery if not
- S1-2 ON  : Boot from USB / recovery mode
- S1-2 OFF : Boot from NAND if available
sheet 17
- 3.3V, 270mA
- 1.8V, 225mA
- 1.2V, 200mA
- 1.5V, 160mA
- Start button
- Power supply decoupling.
- Place close to DC/DC and i.MX28 regulator outputs
- JTAG connector - needs an adapter for std. 20 pin header
- JTAG chaining alternatives
- Default : JTAG->MX->ZB->JTAG
